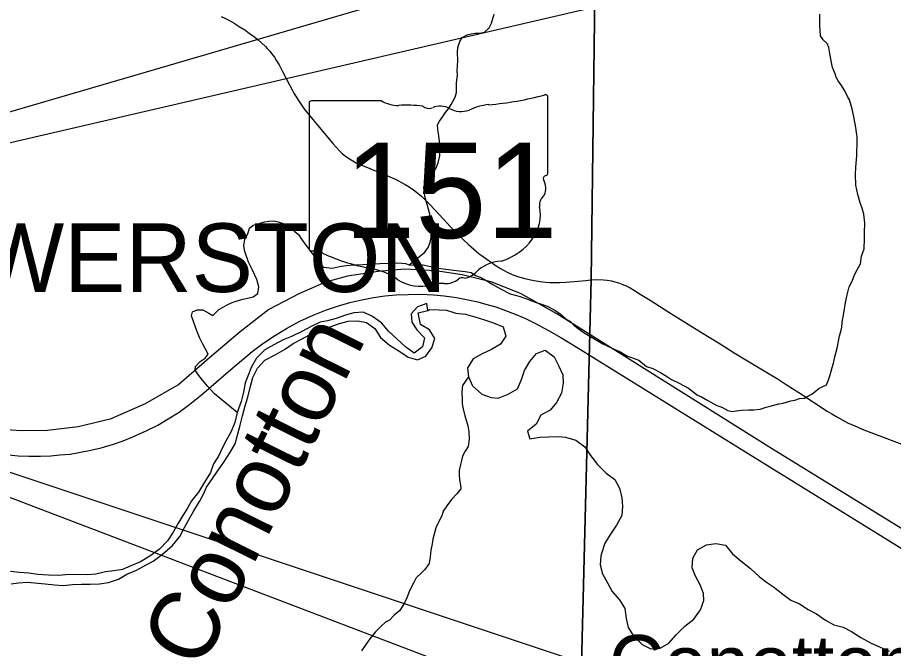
# Model space of a CAD drawing. Extents: x -7.1 to 34, y 0 to 22.
# Drawn here: x 5.914 to 7.123, y 16.774 to 17.646 of the extents above; entities that cross this region are included whole.
import ezdxf

# ---------------------------------------------------------------- set-up
doc = ezdxf.new("R2010")
doc.units = 0
for name, color, linetype in [('GM_X_Corporation_Text', 7, 'Continuous'), ('GM_X_Major_River', 7, 'Continuous'), ('GM_X_Major_River_Text', 7, 'Continuous'), ('GM_X_Minor_River', 7, 'Continuous'), ('GM_X_Rail_Line', 7, 'Continuous'), ('GM_X_State_Location', 7, 'Continuous'), ('GM_X_State_Route', 7, 'Continuous'), ('GM_X_State_Shield', 7, 'Continuous'), ('GM_X_Township_Road', 7, 'Continuous'), ('GM_X_Unincorporated_Text', 7, 'Continuous'), ('SH_Text', 7, 'Continuous')]:
    doc.layers.add(name, color=color, linetype=linetype)

msp = doc.modelspace()

# ---------------------------------------------------------------- linework, layer by layer
at = {"layer": 'GM_X_Major_River'}
for points in [[(6.4802, 17.241), (6.479, 17.2508), (6.4661, 17.2461), (6.4572, 17.2364), (6.4583, 17.2249), (6.465, 17.2146), (6.4757, 17.2033), (6.4729, 17.1908), (6.4616, 17.1823), (6.4497, 17.1909), (6.4259, 17.2126), (6.4163, 17.2239), (6.404, 17.2328), (6.3914, 17.2387), (6.3785, 17.2378), (6.3668, 17.2347), (6.3539, 17.2303), (6.3418, 17.2268), (6.3319, 17.2251), (6.3195, 17.2189), (6.3067, 17.2123), (6.2923, 17.2053), (6.2806, 17.2006), (6.2681, 17.1936), (6.2553, 17.187), (6.2441, 17.1755), (6.237, 17.1633), (6.2322, 17.1507), (6.2285, 17.1411), (6.226, 17.1286), (6.2228, 17.1157), (6.2172, 17.1004), (6.214, 17.0867), (6.2092, 17.0741), (6.2018, 17.0608), (6.1962, 17.0501), (6.1914, 17.0401), (6.1847, 17.0294), (6.1807, 17.0176), (6.1721, 17.0042), (6.1639, 16.9901), (6.1542, 16.9782), (6.149, 16.9683), (6.1423, 16.9583), (6.1356, 16.9465), (6.1289, 16.935), (6.1214, 16.9232), (6.1102, 16.9117), (6.097, 16.902), (6.0838, 16.8939), (6.0706, 16.8884), (6.0589, 16.8837), (6.0471, 16.8817), (6.0357, 16.8804), (6.0225, 16.8772), (6.0107, 16.8763), (5.9849, 16.8768), (5.9713, 16.8751), (5.9568, 16.8757), (5.9424, 16.8766), (5.9298, 16.8784), (5.9169, 16.8794), (5.9044, 16.8807)], [(5.9053, 16.8637), (5.9156, 16.8653), (5.9281, 16.8662), (5.9421, 16.8645), (5.9524, 16.8638), (5.9653, 16.8625), (5.9779, 16.8615), (5.99, 16.8628), (6.0025, 16.8633), (6.0147, 16.8631), (6.0272, 16.8636), (6.0397, 16.8657), (6.0537, 16.87), (6.065, 16.877), (6.0786, 16.8828), (6.0918, 16.8898), (6.1016, 16.8952), (6.1144, 16.9045), (6.128, 16.9168), (6.1381, 16.9291), (6.1447, 16.9413), (6.1518, 16.955), (6.1574, 16.9646), (6.1652, 16.9776), (6.1708, 16.9875), (6.1752, 16.9971), (6.1842, 17.0104), (6.1927, 17.0223), (6.1991, 17.0319), (6.2073, 17.0445), (6.2144, 17.0571), (6.2176, 17.0689), (6.2216, 17.0826), (6.2245, 17.0956), (6.2285, 17.1093), (6.2322, 17.1215), (6.2354, 17.1348), (6.2387, 17.1485), (6.2454, 17.1615), (6.2555, 17.1726), (6.2698, 17.18), (6.2827, 17.1873), (6.2947, 17.1954), (6.3072, 17.2021), (6.3211, 17.2098), (6.3328, 17.2153), (6.3457, 17.2188), (6.3585, 17.2232), (6.3703, 17.2263), (6.3836, 17.2269), (6.3957, 17.2248), (6.4072, 17.2162), (6.415, 17.2037), (6.4276, 17.1933), (6.4403, 17.1854), (6.4533, 17.1765), (6.4662, 17.1732), (6.4776, 17.1779), (6.4858, 17.1898), (6.4902, 17.2027), (6.4828, 17.2144), (6.4702, 17.2219), (6.4669, 17.2381)], [(6.4669, 17.2381), (6.4802, 17.241)], [(6.4802, 17.241), (6.4829, 17.2425), (6.4958, 17.2419), (6.506, 17.2417), (6.519, 17.2376), (6.5323, 17.2363), (6.5453, 17.2326), (6.5571, 17.2286), (6.5712, 17.2242), (6.5842, 17.2187), (6.5881, 17.2055), (6.5806, 17.1947), (6.5682, 17.1874), (6.5554, 17.1815), (6.5429, 17.1745), (6.5351, 17.1619), (6.5364, 17.1494), (6.5422, 17.137), (6.5549, 17.1257), (6.5679, 17.121), (6.5774, 17.1203), (6.591, 17.1254), (6.6042, 17.1328), (6.6097, 17.1458), (6.6137, 17.1583), (6.6212, 17.1706), (6.6302, 17.1817), (6.6423, 17.1864), (6.6549, 17.1774), (6.6607, 17.1654), (6.6666, 17.1525), (6.6671, 17.1408), (6.6646, 17.1271), (6.6579, 17.1141), (6.649, 17.1034), (6.6361, 17.0967), (6.6298, 17.0841), (6.6178, 17.0745), (6.6213, 17.0639), (6.635, 17.0664), (6.6467, 17.0665), (6.6604, 17.0671), (6.6703, 17.0664), (6.6844, 17.062), (6.697, 17.0531), (6.7048, 17.041), (6.7144, 17.0286), (6.7263, 17.0166), (6.7382, 17.0077), (6.7448, 16.996), (6.748, 16.9827), (6.7489, 16.9706), (6.7479, 16.9581), (6.7405, 16.9447), (6.7323, 16.9321), (6.7245, 16.9199), (6.7205, 16.9069)], [(6.7205, 16.9069), (6.719, 16.902), (6.718, 16.8898), (6.7212, 16.8777), (6.7282, 16.8649), (6.7348, 16.8532), (6.7448, 16.8416), (6.7521, 16.8295), (6.7538, 16.8159), (6.7566, 16.8034), (6.7644, 16.791), (6.7759, 16.7801), (6.7881, 16.7738), (6.8007, 16.7751), (6.8127, 16.7817), (6.8228, 16.7932), (6.8348, 16.8055), (6.8473, 16.8151), (6.8566, 16.8278), (6.8614, 16.8407), (6.8609, 16.8502), (6.8562, 16.8623), (6.8496, 16.8743), (6.8453, 16.886), (6.8462, 16.8993), (6.8526, 16.9108), (6.865, 16.9178), (6.8779, 16.9194), (6.8912, 16.9173), (6.9005, 16.9053), (6.912, 16.8956), (6.9254, 16.8847), (6.9381, 16.8735), (6.9477, 16.866), (6.9572, 16.8597), (6.9703, 16.8496), (6.9814, 16.8414), (6.9932, 16.8359), (7.0051, 16.8284), (7.0165, 16.8225), (7.0292, 16.8135), (7.0406, 16.8072), (7.0532, 16.804), (7.0651, 16.7977), (7.0777, 16.7895), (7.0911, 16.7824), (7.1044, 16.7765), (7.1167, 16.7706)]]:
    msp.add_lwpolyline(points, dxfattribs=at)
at = {"layer": 'GM_X_Minor_River'}
for points in [[(6.4548, 17.3041), (6.4761, 17.3219), (6.481, 17.3281), (6.4835, 17.335), (6.4849, 17.3418), (6.4847, 17.3597), (6.4838, 17.3708), (6.4829, 17.3761), (6.4813, 17.381), (6.4798, 17.3863), (6.4769, 17.3969), (6.4753, 17.4061), (6.4748, 17.4118), (6.477, 17.4171), (6.4804, 17.4221), (6.4882, 17.4329), (6.4919, 17.4379), (6.4952, 17.4467), (6.497, 17.4548), (6.4976, 17.4647), (6.4963, 17.4749), (6.495, 17.4856), (6.4942, 17.4909), (6.4937, 17.4974), (6.4967, 17.5027), (6.5011, 17.5089), (6.5041, 17.5139), (6.5089, 17.5197), (6.5126, 17.5258), (6.5181, 17.5355), (6.5199, 17.542), (6.5198, 17.5503), (6.5201, 17.5553), (6.5211, 17.566), (6.521, 17.5717), (6.5216, 17.5865), (6.5214, 17.5972), (6.5217, 17.6041), (6.5243, 17.6125), (6.5276, 17.6179), (6.5347, 17.6218), (6.54, 17.623), (6.5457, 17.6239), (6.5521, 17.6243), (6.5585, 17.6256), (6.5649, 17.6314), (6.5682, 17.6379), (6.5718, 17.6505)], [(6.6878, 17.2162), (6.6962, 17.2102), (6.7072, 17.2039), (6.7217, 17.1953), (6.7278, 17.1924), (6.7393, 17.1869), (6.7442, 17.185), (6.7557, 17.1783), (6.7614, 17.1761), (6.7717, 17.1725), (6.782, 17.1639), (6.7908, 17.161), (6.8014, 17.1554), (6.811, 17.1495), (6.8167, 17.1461), (6.827, 17.141), (6.84, 17.1339), (6.8526, 17.1242), (6.8579, 17.122), (6.8667, 17.1168), (6.8793, 17.1098), (6.8858, 17.1076), (6.8942, 17.1031), (6.9003, 17.1017), (6.9056, 17.1025), (6.9131, 17.1034), (6.9226, 17.1039), (6.9301, 17.1041), (6.9388, 17.1049), (6.9471, 17.1077), (6.9528, 17.109), (6.9645, 17.1122), (6.9705, 17.1134), (6.9814, 17.1166), (6.9867, 17.1175), (6.9931, 17.1195), (7, 17.12), (7.0048, 17.1227), (7.0101, 17.1254), (7.0198, 17.1336), (7.0255, 17.1363), (7.0304, 17.1383), (7.0333, 17.1452), (7.0355, 17.1521), (7.0383, 17.1624), (7.0401, 17.1686), (7.0419, 17.1773), (7.0452, 17.1892), (7.0473, 17.201), (7.0483, 17.206), (7.0501, 17.2121), (7.0516, 17.2182), (7.0522, 17.2251), (7.0543, 17.2377), (7.0564, 17.2522), (7.0589, 17.2629), (7.0617, 17.274), (7.0658, 17.2817), (7.0691, 17.2905), (7.0728, 17.2974), (7.0772, 17.3055), (7.0789, 17.3161), (7.0822, 17.3261), (7.0828, 17.3402), (7.083, 17.349), (7.0832, 17.3619), (7.0819, 17.3741), (7.0795, 17.3824), (7.0768, 17.39), (7.0736, 17.4014), (7.0711, 17.4143), (7.0705, 17.4291), (7.0711, 17.4391), (7.0724, 17.4547), (7.0729, 17.476), (7.0728, 17.4814), (7.072, 17.4871), (7.0707, 17.4939), (7.0687, 17.5061), (7.0658, 17.5197), (7.0623, 17.5319), (7.0595, 17.5368), (7.0556, 17.5443), (7.0502, 17.553), (7.0464, 17.5583), (7.0436, 17.5632), (7.0424, 17.5681), (7.0389, 17.5768), (7.0369, 17.586), (7.0348, 17.5958), (7.0336, 17.6042), (7.0312, 17.6099), (7.0259, 17.6151), (7.022, 17.6204), (7.021, 17.6356), (7.0212, 17.6505)], [(6.1839, 17.2343), (6.1922, 17.2426), (6.197, 17.2453), (6.2034, 17.2492), (6.2106, 17.2524), (6.2159, 17.254), (6.2253, 17.2568), (6.234, 17.2588), (6.2396, 17.2601), (6.246, 17.2647), (6.2474, 17.2739), (6.2446, 17.2841), (6.2383, 17.297), (6.2329, 17.308), (6.2281, 17.3224), (6.2265, 17.3303), (6.2279, 17.3395), (6.232, 17.3468), (6.2345, 17.3548), (6.2393, 17.3591), (6.2492, 17.3619), (6.2548, 17.3635), (6.2612, 17.3644), (6.2673, 17.3648), (6.2741, 17.3638), (6.2836, 17.3605), (6.2897, 17.3568), (6.297, 17.3504), (6.302, 17.3459), (6.3063, 17.3395), (6.3121, 17.3312), (6.3178, 17.3241), (6.3228, 17.3177), (6.3263, 17.312), (6.3294, 17.3071), (6.3363, 17.3011), (6.3485, 17.2998), (6.3609, 17.3023), (6.3681, 17.3031), (6.373, 17.3036), (6.381, 17.3041), (6.4003, 17.3051), (6.4143, 17.3061), (6.4377, 17.3068), (6.4445, 17.3066), (6.4495, 17.3059), (6.4548, 17.3041), (6.4609, 17.3038), (6.4661, 17.3046), (6.4733, 17.3043), (6.4821, 17.3022), (6.4954, 17.2997), (6.5014, 17.2987), (6.5234, 17.2959), (6.5318, 17.2949), (6.5401, 17.2935), (6.5462, 17.2894), (6.5527, 17.2872), (6.5619, 17.2821), (6.5699, 17.2772), (6.5806, 17.2709), (6.5939, 17.2643), (6.6076, 17.2603), (6.6179, 17.257), (6.6297, 17.2522), (6.6358, 17.2504), (6.6449, 17.2471), (6.6556, 17.2416), (6.6644, 17.2356), (6.6713, 17.2292), (6.6774, 17.2259), (6.6816, 17.221), (6.6878, 17.2162)], [(6.2172, 17.1004), (6.1859, 17.1263), (6.177, 17.1361), (6.1693, 17.1448), (6.1632, 17.1534), (6.1593, 17.1587), (6.1596, 17.164), (6.1663, 17.1706), (6.1731, 17.1753), (6.1771, 17.1807), (6.1732, 17.1886), (6.1701, 17.1947), (6.1655, 17.2041), (6.1615, 17.2132), (6.1576, 17.2246), (6.1544, 17.2337), (6.1559, 17.2394), (6.1619, 17.2421), (6.1698, 17.2419), (6.1782, 17.2374), (6.1838, 17.2344)], [(6.5364, 17.1494), (6.528, 17.1376), (6.5273, 17.1288), (6.5279, 17.1182), (6.5279, 17.1121), (6.5292, 17.1052), (6.5316, 17.0957), (6.5336, 17.0882), (6.5356, 17.0821), (6.5368, 17.0734), (6.5374, 17.0635), (6.536, 17.0535), (6.5319, 17.047), (6.5282, 17.0401), (6.5268, 17.034), (6.5254, 17.0283), (6.5236, 17.0202), (6.5237, 17.0149), (6.5242, 17.0073), (6.5254, 17.0001), (6.5258, 16.9951), (6.5206, 16.9878), (6.5128, 16.9801), (6.5065, 16.9716), (6.5017, 16.9643), (6.4995, 16.9578), (6.4962, 16.9505), (6.4914, 16.9409), (6.4893, 16.9325), (6.4875, 16.9252), (6.4864, 16.9191), (6.4847, 16.9104), (6.4836, 16.9012), (6.4823, 16.8917), (6.4763, 16.8836), (6.4715, 16.8789), (6.4644, 16.872), (6.4611, 16.8654), (6.4552, 16.8543), (6.4515, 16.8444), (6.4482, 16.8375), (6.4419, 16.8271), (6.4341, 16.8205), (6.4274, 16.8135), (6.4221, 16.8108), (6.4161, 16.8054), (6.4075, 16.7969), (6.4005, 16.7876), (6.3938, 16.7784), (6.389, 16.7714)]]:
    msp.add_lwpolyline(points, dxfattribs=at)
at = {"layer": 'GM_X_Rail_Line'}
for points in [[(7.4325, 16.7577), (7.35, 16.8072), (7.1569, 16.9257), (6.9544, 17.0508), (6.6583, 17.2367), (6.6091, 17.2642), (6.5693, 17.2801), (6.5279, 17.2906), (6.4912, 17.296), (6.4482, 17.298), (6.4117, 17.2952), (6.3697, 17.2886), (6.3394, 17.2801), (6.3022, 17.2643), (6.2611, 17.2425), (6.2216, 17.2119), (6.1793, 17.1758), (6.1367, 17.1389), (6.0906, 17.1124), (6.0421, 17.0909), (5.9978, 17.0803), (5.9556, 17.0754), (5.9192, 17.075), (5.879, 17.0776)], [(5.8978, 17.0422), (5.9153, 17.0407), (5.9297, 17.0401), (5.946, 17.0398), (5.9602, 17.0407), (5.9728, 17.0417), (5.987, 17.043), (5.9989, 17.045), (6.0156, 17.0485), (6.0299, 17.0516), (6.0466, 17.0568), (6.0601, 17.0613), (6.0735, 17.0666), (6.0916, 17.0749), (6.1079, 17.083), (6.1223, 17.0915), (6.1373, 17.1009), (6.1521, 17.1119), (6.168, 17.1246), (6.2088, 17.1599), (6.238, 17.1845), (6.2511, 17.1942), (6.2677, 17.2056), (6.2854, 17.2163), (6.3038, 17.2265), (6.322, 17.2345), (6.3404, 17.2419), (6.3557, 17.2471), (6.3729, 17.252), (6.3891, 17.2559), (6.4052, 17.2591), (6.421, 17.2612), (6.4369, 17.2627), (6.4533, 17.2634), (6.4708, 17.2635), (6.4884, 17.2628), (6.503, 17.2616), (6.52, 17.2592), (6.536, 17.2561), (6.5495, 17.253), (6.5619, 17.2496), (6.5744, 17.246), (6.5877, 17.2412), (6.6007, 17.2361), (6.6141, 17.2304), (6.629, 17.2231), (6.6467, 17.2137), (6.664, 17.2037), (6.6852, 17.191), (6.932, 17.0377), (7.1815, 16.8829)]]:
    msp.add_lwpolyline(points, dxfattribs=at)
at = {"layer": 'GM_X_State_Route'}
for points in [[(6.1954, 17.6472), (6.2003, 17.6448), (6.2069, 17.6414), (6.2133, 17.6377), (6.2202, 17.6335), (6.228, 17.6285), (6.2341, 17.6243), (6.24, 17.6199), (6.2463, 17.6149), (6.251, 17.6107), (6.2564, 17.6055), (6.2588, 17.6029), (6.2622, 17.5991), (6.2661, 17.5944), (6.2687, 17.5908), (6.2717, 17.5861), (6.2751, 17.5803), (6.28, 17.5711), (6.2939, 17.5442), (6.2955, 17.5414), (6.3019, 17.531), (6.3045, 17.527), (6.3093, 17.52), (6.3129, 17.5154), (6.3327, 17.4915), (6.3494, 17.4717), (6.3543, 17.466), (6.3589, 17.4611), (6.3616, 17.4585), (6.3655, 17.4552), (6.3689, 17.4527), (6.3721, 17.4506), (6.3768, 17.4478), (6.3815, 17.4452), (6.3858, 17.4432), (6.4002, 17.437), (6.4093, 17.4334), (6.4269, 17.4261), (6.4355, 17.4224), (6.4391, 17.4206), (6.4489, 17.4152), (6.4547, 17.4117), (6.4604, 17.4079), (6.4649, 17.4045), (6.4717, 17.3988), (6.4758, 17.3951), (6.4818, 17.389), (6.4909, 17.3791), (6.5123, 17.3561), (6.5166, 17.3517), (6.5298, 17.3386), (6.5366, 17.3322), (6.5438, 17.3257), (6.551, 17.3196), (6.5538, 17.3175), (6.5694, 17.3063), (6.5718, 17.3047), (6.5807, 17.2992), (6.5848, 17.2969), (6.5917, 17.2933), (6.5967, 17.291), (6.6041, 17.2882), (6.6092, 17.2865), (6.6143, 17.2852), (6.6204, 17.2838), (6.6272, 17.2824), (6.6354, 17.2811), (6.6426, 17.2803), (6.6489, 17.2798), (6.6561, 17.2796), (6.6626, 17.2797), (6.6709, 17.2801), (6.688, 17.2818), (6.6982, 17.2828), (6.7049, 17.2835), (6.7121, 17.2839)], [(6.7121, 17.2839), (6.7226, 17.2837), (6.728, 17.2832), (6.7339, 17.2821), (6.7384, 17.2809), (6.7446, 17.2791), (6.7495, 17.2772), (6.7548, 17.2748), (6.7595, 17.2723), (6.7656, 17.2687), (6.7734, 17.2637), (6.7869, 17.2552), (6.8131, 17.2388), (6.8373, 17.2237), (6.8581, 17.2109), (6.8837, 17.1951), (6.9032, 17.1828), (6.9489, 17.1549), (6.9636, 17.1462), (6.9747, 17.1392), (6.9923, 17.1277), (7.0312, 17.1023), (7.0377, 17.0985), (7.0455, 17.0937), (7.053, 17.0895), (7.0603, 17.0858), (7.0684, 17.0822), (7.0797, 17.0775), (7.0918, 17.0727), (7.1382, 17.0553)]]:
    msp.add_lwpolyline(points, dxfattribs=at)
at = {"layer": 'GM_X_State_Shield'}
for p, q in [((6.3165, 17.5273), (6.3165, 17.3271)), ((6.4163, 17.5307), (6.3198, 17.5307)), ((6.6461, 17.431), (6.6461, 17.5357)), ((6.6461, 17.431), (6.6461, 17.431))]:
    msp.add_line(p, q, dxfattribs=at)
for centre, major_axis, start_param, end_param in [((6.5287, 17.8035), (0.3495, 0), 4.814394, 5.042369), ((6.6425, 17.5361), (0.00367, 0), 6.141152, 7.989035), ((6.3203, 17.5277), (0.00382, 0), 1.712693, 3.28349), ((6.4393, 17.5539), (0.037, 0), 4.042523, 4.731795), ((6.4516, 17.4183), (0.133, 0), 1.404758, 1.657858), ((6.4974, 17.5056), (0.0222, 0), 0.950623, 2.079405), ((6.5733, 17.4696), (0.0703, 0), 1.699011, 2.107814), ((6.4817, 17.5287), (0.0107, 0), 3.836095, 5.185415), ((6.5261, 17.5373), (0.0267, 0), 4.081561, 5.145723), ((6.6453, 17.4233), (0.00568, 0), 1.883978, 3.671073), ((6.6422, 17.4306), (0.00393, 0), 5.05454, 6.418171), ((6.6091, 17.4101), (0.0341, 0), 5.934695, 6.695948), ((6.6593, 17.3872), (0.0248, 0), 2.387724, 3.262537), ((6.5483, 17.3738), (0.0874, 0), 5.101752, 6.440018), ((6.3203, 17.3267), (0.00385, 0), 3.00124, 4.508301), ((6.3209, 17.3472), (0.0294, 0), 4.665946, 4.897461), ((6.3269, 17.3156), (0.0106, 0), 0.519207, 1.627899), ((6.4608, 17.4954), (0.2524, 0), 4.195997, 4.488961), ((6.5852, 17.271), (0.0479, 0), 1.647645, 2.488434), ((6.3855, 17.2372), (0.079, 0), 0.823519, 1.323587), ((6.4709, 17.3146), (0.0501, 0), 4.026481, 4.996735), ((6.5035, 17.2996), (0.0267, 0), 4.691044, 5.507374), ((6.5277, 17.2802), (0.00752, 0), 1.147584, 2.315152), ((6.5245, 17.3077), (0.0282, 0), 4.937069, 5.64225), ((6.4999, 17.2454), (0.0412, 0), 1.495662, 1.94098)]:
    msp.add_ellipse(centre, major_axis=major_axis, ratio=0.8, start_param=start_param, end_param=end_param, dxfattribs=at)
at = {"layer": 'GM_X_Township_Road'}
msp.add_lwpolyline([(2.1, 17.7253), (2.1, 14.1), (6.633, 14.1), (6.6565, 15.1357), (6.6586, 15.2372), (6.6748, 15.9993), (6.6822, 16.3488), (6.7058, 17.2839), (6.7118, 17.7486)], dxfattribs=at)
msp.add_lwpolyline([(6.633, 14.1), (8.9, 14.1), (8.9, 17.7079), (8.6668, 17.7136), (8.4472, 17.7189), (7.7202, 17.7285), (6.7118, 17.7486), (6.7058, 17.2839), (6.6822, 16.3488), (6.6748, 15.9993), (6.6586, 15.2372), (6.6565, 15.1357)], close=True, dxfattribs=at)
at = {"layer": 'SH_Text'}
for points in [[(5.1887, 17.3067), (9.3652, 18.5286), (9.3652, 18.2766)], [(5.1735, 17.2614), (9.3262, 15.8766), (9.3261, 15.6767)]]:
    msp.add_lwpolyline(points, close=True, dxfattribs=at)

# ---------------------------------------------------------------- texts
at = {"layer": 'GM_X_Corporation_Text'}
msp.add_text('BOWERSTON', height=0.0947, rotation=0, dxfattribs=at).set_placement((5.6761, 17.2667))
at = {"layer": 'GM_X_Major_River_Text'}
msp.add_text('Conotton', height=0.09472, rotation=63.5646, dxfattribs=at).set_placement((6.1668, 16.7422))
at = {"layer": 'GM_X_State_Location'}
for s in ['s', 'r']:
    msp.add_text(s, height=0.000189, dxfattribs=at).set_placement((6.4776, 17.4139))
msp.add_text('151', height=0.000189, rotation=0, dxfattribs=at).set_placement((6.4108, 17.4001))
at = {"layer": 'GM_X_State_Shield'}
msp.add_text('151', height=0.13184, dxfattribs=at).set_placement((6.3651, 17.3412))
at = {"layer": 'GM_X_Unincorporated_Text'}
msp.add_text('Conotton', height=0.07898, rotation=0, dxfattribs=at).set_placement((6.7299, 16.714))

doc.saveas('drawing.dxf')
